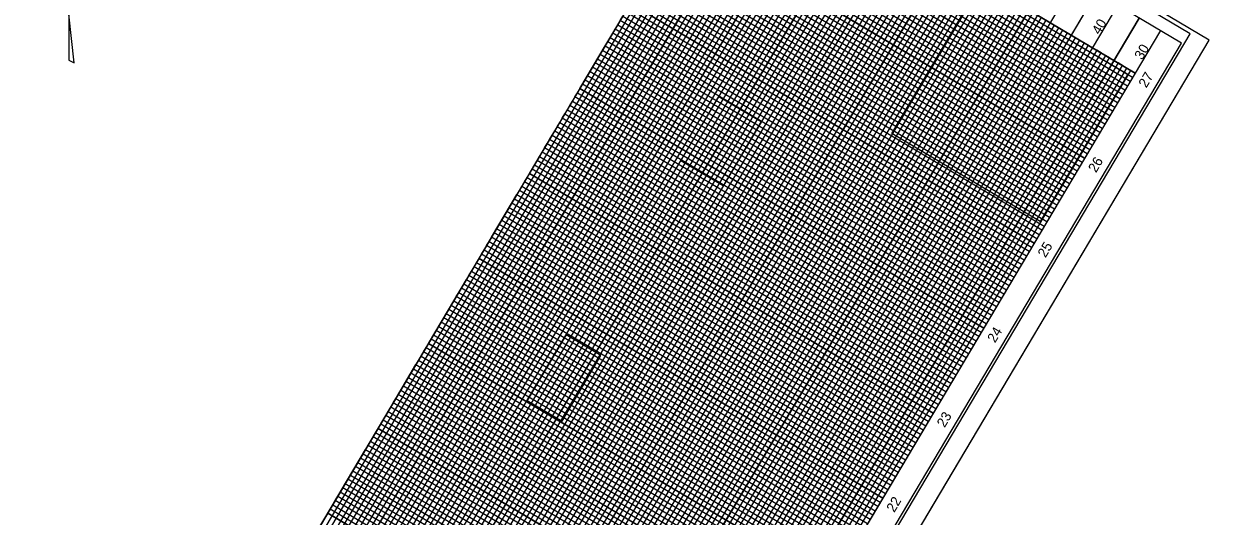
# Model space of a CAD drawing. Extents: x 2137081 to 2142019, y 404041 to 411238.
# Drawn here: x 2140819 to 2142019, y 410000 to 410499 of the extents above; entities that cross this region are included whole.
import ezdxf

# ---------------------------------------------------------------- set-up
doc = ezdxf.new("R2010")
doc.units = 0
for name, color, linetype in [('CTL North Arrow NAD 83 NA 2011 CELL', 7, 'Continuous'), ('Exist Vertical Profile Horizontal Axis Label Major', 7, 'Continuous'), ('Exist Vertical Profile Vertical Axis Label', 7, 'Continuous'), ('Prop Grid Mask', 7, 'Continuous'), ('Sheet Clip Boundary CELL', 7, 'Continuous'), ('Sheet Cutting Line CELL', 7, 'Continuous'), ('Sheet DOT Grid CELL', 7, 'Continuous'), ('Sheet Layout Profile Border Port 2', 7, 'Continuous'), ('Sheet Plan And Profile CELL', 7, 'Continuous'), ('Sheet Plot Border Inside CELL', 7, 'Continuous'), ('Sheet Plot Border Outside CELL', 7, 'Continuous'), ('Sheet Profile Grid Major CELL', 7, 'Continuous'), ('Sheet Profile Grid Middle CELL', 7, 'Continuous'), ('Sheet Profile Grid Minor CELL', 7, 'Continuous')]:
    doc.layers.add(name, color=color, linetype=linetype)

msp = doc.modelspace()

# ---------------------------------------------------------------- linework, layer by layer
at = {"layer": 'CTL North Arrow NAD 83 NA 2011 CELL'}
msp.add_lwpolyline([(2140864.9, 410461.8), (2140870.4, 410459.1), (2140864.9, 410508.5)], close=True, dxfattribs=at)
at = {"layer": 'Prop Grid Mask'}
for points in [[(2141936.1, 410447.6), (2141847.6, 410298.5), (2141697.4, 410387.7), (2141785.9, 410536.8)], [(2141484, 410360.1), (2141522.5, 410425), (2141565.2, 410399.7), (2141526.7, 410334.8)], [(2141363.9, 410096.7), (2141403.2, 410163), (2141368.1, 410183.9), (2141328.7, 410117.5)]]:
    msp.add_lwpolyline(points, close=True, dxfattribs=at)
at = {"layer": 'Sheet Clip Boundary CELL'}
msp.add_lwpolyline([(2140795, 409444.3), (2141473.2, 410587), (2141453.9, 410598.4), (2141513.1, 410698), (2141213, 410886.1), (2141134.8, 410754.3), (2141040.5, 410810.3), (2140938.2, 410638), (2140883.3, 410670.6), (2140322, 409725)], close=True, dxfattribs=at)
at = {"layer": 'Sheet Cutting Line CELL'}
msp.add_line((2141159.3, 409034.5), (2142018.6, 410482.2), dxfattribs=at)
at = {"layer": 'Sheet DOT Grid CELL'}
for p, q in [((2140795, 409444.3), (2141560.6, 410734.2)), ((2140838, 409418.8), (2141603.6, 410708.7)), ((2141535.1, 410691.2), (2141943.6, 410448.8)), ((2140881, 409393.3), (2141646.6, 410683.2)), ((2140924, 409367.8), (2141689.6, 410657.7)), ((2141509.6, 410648.2), (2141918, 410405.8)), ((2140967, 409342.2), (2141732.6, 410632.1)), ((2141010, 409316.7), (2141775.6, 410606.6)), ((2141484, 410605.2), (2141892.5, 410362.8)), ((2141053, 409291.2), (2141818.6, 410581.1)), ((2141458.5, 410562.2), (2141867, 410319.8)), ((2141096, 409265.7), (2141861.6, 410555.6)), ((2141139, 409240.2), (2141904.6, 410530.1)), ((2141433, 410519.2), (2141841.5, 410276.8)), ((2141182, 409214.6), (2141947.6, 410504.5)), ((2141407.5, 410476.2), (2141816, 410233.8)), ((2141382, 410433.2), (2141790.4, 410190.8)), ((2141356.4, 410390.2), (2141764.9, 410147.8)), ((2141330.9, 410347.3), (2141739.4, 410104.8)), ((2141305.4, 410304.3), (2141713.9, 410061.8)), ((2141279.9, 410261.3), (2141688.4, 410018.8)), ((2141254.4, 410218.3), (2141662.8, 409975.8)), ((2141228.8, 410175.3), (2141637.3, 409932.8)), ((2141203.3, 410132.3), (2141611.8, 409889.8)), ((2141177.8, 410089.3), (2141586.3, 409846.8)), ((2141152.3, 410046.3), (2141560.8, 409803.8)), ((2141126.8, 410003.3), (2141535.2, 409760.8))]:
    msp.add_line(p, q, dxfattribs=at)
at = {"layer": 'Sheet Layout Profile Border Port 2'}
msp.add_lwpolyline([(2140820.5, 409487.3), (2141535.1, 410691.2), (2141943.6, 410448.8), (2141229, 409244.9)], close=True, dxfattribs=at)
at = {"layer": 'Sheet Plan And Profile CELL'}
msp.add_line((2141969.1, 410491.8), (2141203.5, 409201.9), dxfattribs=at)
msp.add_lwpolyline([(2141087.6, 411014.9), (2140322, 409725), (2141225, 409189.1), (2141990.6, 410479)], close=True, dxfattribs=at)
at = {"layer": 'Sheet Plot Border Inside CELL'}
msp.add_lwpolyline([(2141148.8, 409055.8), (2141999.1, 410488.5), (2141091.9, 411027), (2140241.5, 409594.3)], close=True, dxfattribs=at)
at = {"layer": 'Sheet Plot Border Outside CELL'}
msp.add_lwpolyline([(2141159.3, 409034.5), (2142018.6, 410482.2), (2141077, 411041), (2140217.7, 409593.3)], close=True, dxfattribs=at)
at = {"layer": 'Sheet Profile Grid Major CELL'}
for points in [[(2140795, 409444.3), (2141560.6, 410734.2)], [(2141603.6, 410708.7), (2140838, 409418.8), (2140881, 409393.3), (2141646.6, 410683.2)], [(2141943.6, 410448.8), (2141535.1, 410691.2)], [(2141689.6, 410657.7), (2140924, 409367.8), (2140967, 409342.2), (2141732.6, 410632.1)], [(2141892.5, 410362.8), (2141484, 410605.2), (2141509.6, 410648.2), (2141918, 410405.8)], [(2141775.6, 410606.6), (2141010, 409316.7), (2141053, 409291.2), (2141818.6, 410581.1)], [(2141841.5, 410276.8), (2141433, 410519.2), (2141458.5, 410562.2), (2141867, 410319.8)], [(2141861.6, 410555.6), (2141096, 409265.7), (2141139, 409240.2), (2141904.6, 410530.1)], [(2141947.6, 410504.5), (2141182, 409214.6)], [(2141790.4, 410190.8), (2141382, 410433.2), (2141407.5, 410476.2), (2141816, 410233.8)], [(2141739.4, 410104.8), (2141330.9, 410347.3), (2141356.4, 410390.2), (2141764.9, 410147.8)], [(2141688.4, 410018.8), (2141279.9, 410261.3), (2141305.4, 410304.3), (2141713.9, 410061.8)], [(2141637.3, 409932.8), (2141228.8, 410175.3), (2141254.4, 410218.3), (2141662.8, 409975.8)], [(2141586.3, 409846.8), (2141177.8, 410089.3), (2141203.3, 410132.3), (2141611.8, 409889.8)], [(2141535.2, 409760.8), (2141126.8, 410003.3), (2141152.3, 410046.3), (2141560.8, 409803.8)]]:
    msp.add_lwpolyline(points, dxfattribs=at)
at = {"layer": 'Sheet Profile Grid Middle CELL'}
for p, q in [((2140816.5, 409431.6), (2141582.1, 410721.5)), ((2141625.1, 410695.9), (2140859.5, 409406)), ((2140902.5, 409380.5), (2141668.1, 410670.4)), ((2141711.1, 410644.9), (2140945.5, 409355)), ((2140988.5, 409329.5), (2141754.1, 410619.4)), ((2141797.1, 410593.9), (2141031.5, 409304)), ((2141074.5, 409278.4), (2141840.1, 410568.3)), ((2141883.1, 410542.8), (2141117.5, 409252.9)), ((2141160.5, 409227.4), (2141926.1, 410517.3))]:
    msp.add_line(p, q, dxfattribs=at)
for points in [[(2141905.3, 410384.3), (2141496.8, 410626.7), (2141522.3, 410669.7), (2141930.8, 410427.3)], [(2141854.2, 410298.3), (2141445.8, 410540.7), (2141471.3, 410583.7), (2141879.8, 410341.3)], [(2141803.2, 410212.3), (2141394.7, 410454.7), (2141420.2, 410497.7), (2141828.7, 410255.3)], [(2141752.2, 410126.3), (2141343.7, 410368.8), (2141369.2, 410411.7), (2141777.7, 410169.3)], [(2141701.1, 410040.3), (2141292.6, 410282.8), (2141318.2, 410325.8), (2141726.6, 410083.3)], [(2141650.1, 409954.3), (2141241.6, 410196.8), (2141267.1, 410239.8), (2141675.6, 409997.3)], [(2141599, 409868.3), (2141190.6, 410110.8), (2141216.1, 410153.8), (2141624.6, 409911.3)], [(2141548, 409782.3), (2141139.5, 410024.8), (2141165, 410067.8), (2141573.5, 409825.3)]]:
    msp.add_lwpolyline(points, dxfattribs=at)
at = {"layer": 'Sheet Profile Grid Minor CELL'}
for points in [[(2141539.4, 410688.7), (2140824.8, 409484.8)], [(2141548, 410683.6), (2140833.4, 409479.7), (2140829.1, 409482.2), (2141543.7, 410686.1)], [(2141560.9, 410675.9), (2140846.3, 409472), (2140842, 409474.6), (2140837.7, 409477.1), (2141552.3, 410681)], [(2141933.3, 410431.6), (2141524.9, 410674), (2141527.4, 410678.3), (2141935.9, 410435.9)], [(2141938.5, 410440.2), (2141530, 410682.6), (2141532.5, 410686.9), (2141941, 410444.5)], [(2141569.5, 410670.8), (2140854.9, 409466.9), (2140850.6, 409469.5), (2141565.2, 410673.4)], [(2141582.4, 410663.2), (2140867.8, 409459.2), (2140863.5, 409461.8), (2140859.2, 409464.3), (2141573.8, 410668.3)], [(2141925.7, 410418.7), (2141517.2, 410661.1), (2141519.8, 410665.4), (2141928.2, 410423)], [(2141591, 410658.1), (2140876.4, 409454.1), (2140872.1, 409456.7), (2141586.7, 410660.6)], [(2141603.9, 410650.4), (2140889.3, 409446.5), (2140885, 409449), (2140880.7, 409451.6), (2141595.3, 410655.5)], [(2141920.6, 410410.1), (2141512.1, 410652.5), (2141514.7, 410656.8), (2141923.1, 410414.4)], [(2141612.5, 410645.3), (2140897.9, 409441.4), (2140893.6, 409443.9), (2141608.2, 410647.8)], [(2140910.8, 409433.7), (2140906.5, 409436.3), (2140902.2, 409438.8), (2141616.8, 410642.7)], [(2141912.9, 410397.2), (2141504.5, 410639.6), (2141507, 410643.9), (2141915.5, 410401.5)], [(2141629.7, 410635.1), (2140915.1, 409431.2), (2140910.8, 409433.7), (2141625.4, 410637.6)], [(2141638.3, 410630), (2140923.7, 409426.1), (2140919.4, 409428.6), (2141634, 410632.5)], [(2141907.8, 410388.6), (2141499.4, 410631), (2141501.9, 410635.3), (2141910.4, 410392.9)], [(2141651.2, 410622.3), (2140936.6, 409418.4), (2140932.3, 409421), (2141646.9, 410624.9)], [(2141659.8, 410617.2), (2140945.2, 409413.3), (2140940.9, 409415.9), (2141655.5, 410619.8)], [(2141900.2, 410375.7), (2141491.7, 410618.1), (2141494.3, 410622.4), (2141902.7, 410380)], [(2141672.7, 410609.6), (2140958.1, 409405.7), (2140953.8, 409408.2), (2141668.4, 410612.1)], [(2141681.3, 410604.5), (2140966.7, 409400.5), (2140962.4, 409403.1), (2141677, 410607)], [(2141895.1, 410367.1), (2141486.6, 410609.5), (2141489.1, 410613.8), (2141897.6, 410371.4)], [(2141694.2, 410596.8), (2140979.6, 409392.9), (2140975.3, 409395.4), (2141689.9, 410599.4)], [(2141702.8, 410591.7), (2140988.2, 409387.8), (2140983.9, 409390.3), (2141698.5, 410594.2)], [(2141887.4, 410354.2), (2141478.9, 410596.6), (2141481.5, 410600.9), (2141890, 410358.5)], [(2141715.7, 410584), (2141001.1, 409380.1), (2140996.8, 409382.7), (2141711.4, 410586.6)], [(2141724.3, 410578.9), (2141009.7, 409375), (2141005.4, 409377.6), (2141720, 410581.5)], [(2141882.3, 410345.6), (2141473.8, 410588), (2141476.4, 410592.3), (2141884.9, 410349.9)], [(2141737.2, 410571.3), (2141022.6, 409367.4), (2141018.3, 409369.9), (2141732.9, 410573.8)], [(2141869.5, 410324.1), (2141461.1, 410566.5), (2141463.6, 410570.8), (2141872.1, 410328.4)], [(2141874.6, 410332.7), (2141466.2, 410575.1), (2141468.7, 410579.4), (2141877.2, 410337)], [(2141745.8, 410566.2), (2141031.2, 409362.3), (2141026.9, 409364.8), (2141741.5, 410568.7)], [(2141758.7, 410558.5), (2141044.1, 409354.6), (2141039.8, 409357.2), (2141754.4, 410561.1)], [(2141861.9, 410311.2), (2141453.4, 410553.6), (2141456, 410557.9), (2141864.4, 410315.5)], [(2141767.3, 410553.4), (2141052.7, 409349.5), (2141048.4, 409352.1), (2141763, 410556)], [(2141780.2, 410545.8), (2141065.6, 409341.9), (2141061.3, 409344.4), (2141775.9, 410548.3)], [(2141856.8, 410302.6), (2141448.3, 410545), (2141450.9, 410549.3), (2141859.3, 410306.9)], [(2141788.8, 410540.7), (2141074.2, 409336.7), (2141069.9, 409339.3), (2141784.5, 410543.2)], [(2141801.7, 410533), (2141087.1, 409329.1), (2141082.8, 409331.6), (2141797.4, 410535.6)], [(2141849.1, 410289.7), (2141440.7, 410532.1), (2141443.2, 410536.4), (2141851.7, 410294)], [(2141810.3, 410527.9), (2141095.7, 409324), (2141091.4, 409326.5), (2141806, 410530.4)], [(2141823.2, 410520.2), (2141108.6, 409316.3), (2141104.3, 409318.9), (2141818.9, 410522.8)], [(2141844, 410281.1), (2141435.6, 410523.5), (2141438.1, 410527.8), (2141846.6, 410285.4)], [(2141831.8, 410515.1), (2141117.2, 409311.2), (2141112.9, 409313.8), (2141827.5, 410517.7)], [(2141844.7, 410507.5), (2141130.1, 409303.6), (2141125.8, 409306.1), (2141840.4, 410510)], [(2141836.4, 410268.2), (2141427.9, 410510.6), (2141430.5, 410514.9), (2141838.9, 410272.5)], [(2141173.1, 409278.1), (2141168.8, 409280.6), (2141883.4, 410484.5), (2141874.8, 410489.6), (2141160.2, 409285.7), (2141155.9, 409288.3), (2141870.5, 410492.2), (2141866.2, 410494.7), (2141151.6, 409290.8), (2141147.3, 409293.4), (2141861.9, 410497.3), (2141853.3, 410502.4), (2141138.7, 409298.5), (2141134.4, 409301), (2141849, 410504.9)], [(2141831.3, 410259.6), (2141422.8, 410502), (2141425.3, 410506.3), (2141833.8, 410263.9)], [(2141823.6, 410246.7), (2141415.1, 410489.1), (2141417.7, 410493.4), (2141826.2, 410251)], [(2141224.7, 409247.4), (2141939.3, 410451.3), (2141935, 410453.9), (2141220.4, 409250), (2141216.1, 409252.5), (2141930.7, 410456.4), (2141926.4, 410459), (2141211.8, 409255.1), (2141207.5, 409257.6), (2141203.2, 409260.2), (2141917.8, 410464.1), (2141913.5, 410466.6), (2141198.9, 409262.7), (2141194.6, 409265.3), (2141909.2, 410469.2), (2141904.9, 410471.8), (2141190.3, 409267.8), (2141186, 409270.4), (2141181.7, 409272.9), (2141896.3, 410476.9), (2141892, 410479.4), (2141177.4, 409275.5), (2141173.1, 409278.1), (2141887.7, 410482)], [(2141818.5, 410238.1), (2141410, 410480.5), (2141412.6, 410484.8), (2141821.1, 410242.4)], [(2141805.7, 410216.6), (2141397.3, 410459), (2141399.8, 410463.3), (2141808.3, 410220.9)], [(2141810.8, 410225.2), (2141402.4, 410467.6), (2141404.9, 410471.9), (2141813.4, 410229.5)], [(2141798.1, 410203.7), (2141389.6, 410446.1), (2141392.2, 410450.4), (2141800.6, 410208)], [(2141793, 410195.1), (2141384.5, 410437.5), (2141387.1, 410441.8), (2141795.5, 410199.4)], [(2141785.3, 410182.2), (2141376.9, 410424.6), (2141379.4, 410428.9), (2141787.9, 410186.5)], [(2141780.2, 410173.6), (2141371.8, 410416), (2141374.3, 410420.3), (2141782.8, 410177.9)], [(2141772.6, 410160.7), (2141364.1, 410403.1), (2141366.7, 410407.4), (2141775.1, 410165)], [(2141767.5, 410152.1), (2141359, 410394.5), (2141361.5, 410398.8), (2141770, 410156.4)], [(2141754.7, 410130.6), (2141346.2, 410373.1), (2141348.8, 410377.4), (2141757.3, 410134.9)], [(2141759.8, 410139.2), (2141351.3, 410381.7), (2141353.9, 410385.9), (2141762.4, 410143.5)], [(2141741.9, 410109.1), (2141333.5, 410351.6), (2141336, 410355.9), (2141744.5, 410113.4)], [(2141747, 410117.7), (2141338.6, 410360.2), (2141341.1, 410364.5), (2141749.6, 410122)], [(2141734.3, 410096.2), (2141325.8, 410338.7), (2141328.4, 410343), (2141736.8, 410100.5)], [(2141729.2, 410087.6), (2141320.7, 410330.1), (2141323.3, 410334.4), (2141731.7, 410091.9)], [(2141721.5, 410074.7), (2141313.1, 410317.2), (2141315.6, 410321.5), (2141724.1, 410079)], [(2141716.4, 410066.1), (2141308, 410308.6), (2141310.5, 410312.9), (2141719, 410070.4)], [(2141708.8, 410053.2), (2141300.3, 410295.7), (2141302.9, 410300), (2141711.3, 410057.5)], [(2141703.7, 410044.6), (2141295.2, 410287.1), (2141297.7, 410291.4), (2141706.2, 410048.9)], [(2141690.9, 410023.1), (2141282.4, 410265.6), (2141285, 410269.9), (2141693.5, 410027.4)], [(2141696, 410031.7), (2141287.5, 410274.2), (2141290.1, 410278.5), (2141698.6, 410036)], [(2141678.1, 410001.6), (2141269.7, 410244.1), (2141272.2, 410248.4), (2141680.7, 410005.9)], [(2141683.2, 410010.2), (2141274.8, 410252.7), (2141277.3, 410257), (2141685.8, 410014.5)], [(2141670.5, 409988.7), (2141262, 410231.2), (2141264.6, 410235.5), (2141673, 409993)], [(2141665.4, 409980.1), (2141256.9, 410222.6), (2141259.5, 410226.9), (2141667.9, 409984.4)], [(2141657.7, 409967.2), (2141249.3, 410209.7), (2141251.8, 410214), (2141660.3, 409971.5)], [(2141652.6, 409958.6), (2141244.2, 410201.1), (2141246.7, 410205.4), (2141655.2, 409962.9)], [(2141645, 409945.7), (2141236.5, 410188.2), (2141239.1, 410192.5), (2141647.5, 409950)], [(2141639.9, 409937.1), (2141231.4, 410179.6), (2141233.9, 410183.9), (2141642.4, 409941.4)], [(2141627.1, 409915.6), (2141218.6, 410158.1), (2141221.2, 410162.4), (2141629.7, 409919.9)], [(2141632.2, 409924.2), (2141223.7, 410166.7), (2141226.3, 410171), (2141634.8, 409928.5)], [(2141619.4, 409902.7), (2141211, 410145.2), (2141213.5, 410149.5), (2141622, 409907)], [(2141614.3, 409894.1), (2141205.9, 410136.6), (2141208.4, 410140.9), (2141616.9, 409898.4)], [(2141606.7, 409881.2), (2141198.2, 410123.7), (2141200.8, 410128), (2141609.2, 409885.5)], [(2141601.6, 409872.6), (2141193.1, 410115.1), (2141195.7, 410119.4), (2141604.1, 409876.9)], [(2141593.9, 409859.7), (2141185.5, 410102.2), (2141188, 410106.5), (2141596.5, 409864)], [(2141588.8, 409851.1), (2141180.4, 410093.6), (2141182.9, 410097.9), (2141591.4, 409855.4)], [(2141581.2, 409838.2), (2141172.7, 410080.7), (2141175.3, 410085), (2141583.7, 409842.5)], [(2141576.1, 409829.6), (2141167.6, 410072.1), (2141170.1, 410076.4), (2141578.6, 409833.9)], [(2141563.3, 409808.1), (2141154.8, 410050.6), (2141157.4, 410054.9), (2141565.9, 409812.4)], [(2141568.4, 409816.7), (2141159.9, 410059.2), (2141162.5, 410063.5), (2141571, 409821)], [(2141555.6, 409795.2), (2141147.2, 410037.7), (2141149.7, 410042), (2141558.2, 409799.5)], [(2141550.5, 409786.6), (2141142.1, 410029.1), (2141144.6, 410033.4), (2141553.1, 409790.9)], [(2141542.9, 409773.7), (2141134.4, 410016.2), (2141137, 410020.5), (2141545.4, 409778)], [(2141537.8, 409765.1), (2141129.3, 410007.6), (2141131.9, 410011.9), (2141540.3, 409769.4)]]:
    msp.add_lwpolyline(points, dxfattribs=at)

# ---------------------------------------------------------------- texts
at = {"layer": 'Exist Vertical Profile Horizontal Axis Label Major'}
for s, p in [('27', (2141954.9, 410433.1)), ('26', (2141904, 410347.3)), ('25', (2141852.9, 410261.3)), ('24', (2141801.9, 410175.2)), ('23', (2141750.9, 410089.4)), ('22', (2141699.9, 410003.5))]:
    msp.add_text(s, height=10, rotation=59.3093, dxfattribs=at).set_placement(p)
at = {"layer": 'Exist Vertical Profile Vertical Axis Label'}
for s, p in [('40', (2141907.7, 410486.9)), ('30', (2141950.7, 410461.4))]:
    msp.add_text(s, height=10, rotation=59.3093, dxfattribs=at).set_placement(p)

doc.saveas('drawing.dxf')
